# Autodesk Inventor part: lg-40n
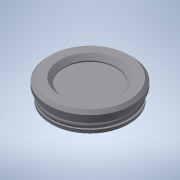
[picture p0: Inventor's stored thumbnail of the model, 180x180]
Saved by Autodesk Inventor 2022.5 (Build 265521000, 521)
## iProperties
Created: 2016-12
Part Number: lg-40n
Material: 一般
Document SubType Name: Modeling
Designer: imaocorp
Density: 1 g/cm^3
Appearance: 既定
Author: imaocorp
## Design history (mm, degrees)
node "lg-40n.x_t1"
node "lg-40n"
node "Base1"
